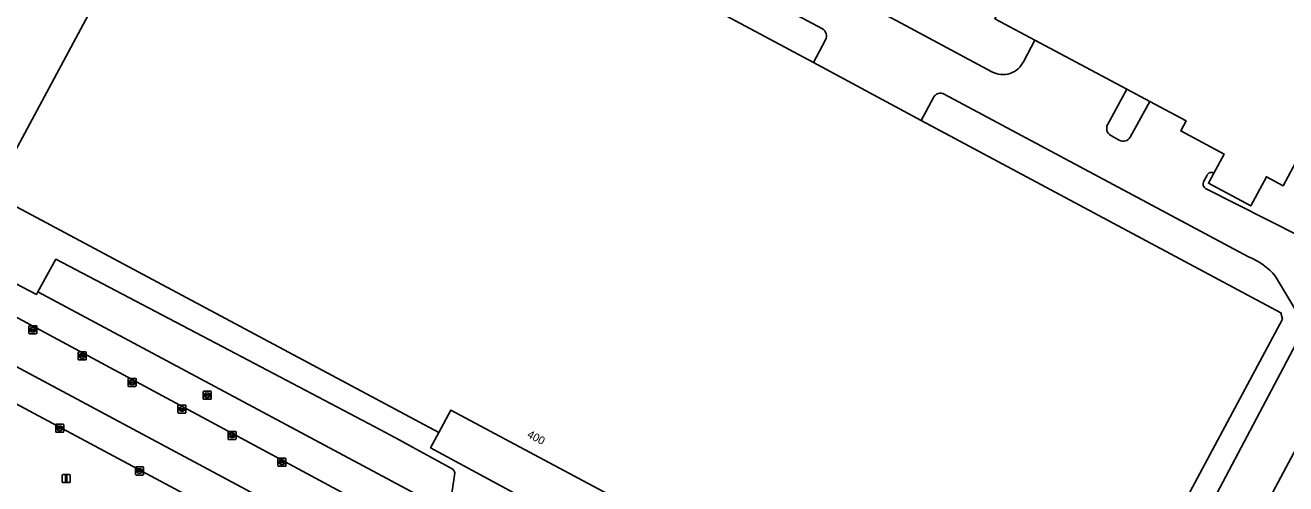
# Model space of a CAD drawing. Extents: x 159489 to 160304, y 383825 to 384531.
# Drawn here: x 159992.1 to 160149.6, y 383929.6 to 383987 of the extents above; entities that cross this region are included whole.
import ezdxf

# ---------------------------------------------------------------- set-up
doc = ezdxf.new("R2010")
doc.units = 0
for name, color, linetype in [('IMGEO_Brandkraan', 7, 'Continuous'), ('IMGEO_Kolk', 7, 'Continuous'), ('IMGEO_Lichtmast', 7, 'Continuous'), ('IMGEO_Pand', 7, 'Continuous'), ('IMGEO_Pand_nummerreeks', 7, 'Continuous'), ('IMGEO_Pand_overbouw', 7, 'Continuous'), ('IMGEO_Parkeervlak_open', 7, 'Continuous'), ('IMGEO_Rijbaan_lokaal_open', 7, 'Continuous'), ('IMGEO_Verkeerseiland_open', 7, 'Continuous'), ('IMGEO_Voetpad_open', 7, 'Continuous')]:
    doc.layers.add(name, color=color, linetype=linetype)

msp = doc.modelspace()

# ---------------------------------------------------------------- linework, layer by layer
at = {"layer": 'IMGEO_Brandkraan'}
for p, q in [((160014.34, 383940.27), (160014.34, 383941.12)), ((160014.42, 383941.2), (160015.27, 383941.2)), ((160014.6, 383940.69), (160014.6, 383940.7)), ((160014.64, 383940.74), (160015.04, 383940.74)), ((160015.04, 383940.65), (160014.64, 383940.65)), ((160014.83, 383940.98), (160014.85, 383940.98)), ((160014.85, 383940.42), (160014.83, 383940.42)), ((160015.08, 383940.7), (160015.08, 383940.69)), ((160015.34, 383941.12), (160015.34, 383940.27)), ((160015.27, 383940.2), (160014.42, 383940.2))]:
    msp.add_line(p, q, dxfattribs=at)
for points in [[(160014.34, 383940.27), (160014.34, 383941.12)], [(160014.42, 383941.2), (160015.27, 383941.2)], [(160015.34, 383941.12), (160015.34, 383940.27)], [(160015.27, 383940.2), (160014.42, 383940.2)]]:
    msp.add_lwpolyline(points, dxfattribs=at)
for centre, radius, start, end in [((160014.42, 383941.12), 0.0765, 91.552, 178.448), ((160014.42, 383941.12), 0.0765, 91.552, 178.448), ((160014.42, 383940.27), 0.0765, 181.552, 268.448), ((160014.42, 383940.27), 0.0765, 181.552, 268.448), ((160014.64, 383940.7), 0.0403, 85.8775, 175.7526), ((160014.64, 383940.69), 0.0366, 178.938, 274.7102), ((160015.05, 383940.7), 0.0386, 1.7309, 96.639), ((160015.04, 383940.7), 0.043, 264.8664, 352.4533), ((160015.27, 383941.12), 0.0765, 1.552, 88.448), ((160015.27, 383941.12), 0.0765, 1.552, 88.448), ((160015.27, 383940.27), 0.0765, 271.552, 358.448), ((160015.27, 383940.27), 0.0765, 271.552, 358.448)]:
    msp.add_arc(centre, radius, start, end, dxfattribs=at)
for centre, major_axis, ratio, start_param, end_param in [((160014.83, 383940.7), (-0.387, 0.002), 0.722429, 4.712389, 7.853982), ((160014.85, 383940.7), (-0.39, 0.002), 0.717154, 1.570796, 4.712389)]:
    msp.add_ellipse(centre, major_axis=major_axis, ratio=ratio, start_param=start_param, end_param=end_param, dxfattribs=at)
at = {"layer": 'IMGEO_Kolk'}
for p, q in [((159992.57, 383948.46), (159992.57, 383949.31)), ((159992.64, 383949.39), (159993.49, 383949.39)), ((159993.49, 383948.38), (159992.64, 383948.38)), ((159992.82, 383948.88), (159992.82, 383948.89)), ((159993.26, 383948.84), (159992.86, 383948.84)), ((159992.87, 383948.93), (159993.27, 383948.93)), ((159993.05, 383949.16), (159993.08, 383949.16)), ((159993.08, 383948.61), (159993.05, 383948.61)), ((159993.31, 383948.89), (159993.31, 383948.88)), ((159993.57, 383949.31), (159993.57, 383948.46)), ((159998.72, 383945.18), (159998.72, 383946.03)), ((159998.8, 383946.11), (159999.65, 383946.11)), ((159999.65, 383945.11), (159998.8, 383945.11)), ((159998.98, 383945.6), (159998.98, 383945.61)), ((159999.02, 383945.65), (159999.42, 383945.65)), ((159999.42, 383945.56), (159999.02, 383945.56)), ((159999.21, 383945.89), (159999.23, 383945.89)), ((159999.23, 383945.33), (159999.21, 383945.33)), ((159999.46, 383945.61), (159999.46, 383945.6)), ((159999.72, 383946.03), (159999.72, 383945.18)), ((160004.97, 383941.87), (160004.97, 383942.72)), ((160005.04, 383942.8), (160005.89, 383942.8)), ((160005.22, 383942.29), (160005.22, 383942.3)), ((160005.66, 383942.25), (160005.26, 383942.25)), ((160005.27, 383942.34), (160005.66, 383942.34)), ((160005.45, 383942.57), (160005.48, 383942.57)), ((160005.48, 383942.02), (160005.45, 383942.02)), ((160005.71, 383942.3), (160005.71, 383942.29)), ((160005.97, 383942.72), (160005.97, 383941.87)), ((160005.89, 383941.79), (160005.04, 383941.79)), ((160011.19, 383938.54), (160011.19, 383939.4)), ((160011.26, 383939.47), (160012.12, 383939.47)), ((160011.45, 383938.96), (160011.45, 383938.98)), ((160011.49, 383939.01), (160011.89, 383939.01)), ((160011.89, 383938.93), (160011.49, 383938.93)), ((160011.7, 383938.69), (160011.67, 383938.69)), ((160011.68, 383939.25), (160011.7, 383939.25)), ((160011.93, 383938.98), (160011.93, 383938.96)), ((160012.19, 383939.4), (160012.19, 383938.54)), ((160012.12, 383938.47), (160011.26, 383938.47)), ((159995.93, 383936.14), (159995.93, 383936.99)), ((159996, 383937.07), (159996.85, 383937.07)), ((159996.85, 383936.06), (159996, 383936.06)), ((159996.19, 383936.56), (159996.19, 383936.57)), ((159996.23, 383936.61), (159996.63, 383936.61)), ((159996.62, 383936.52), (159996.23, 383936.52)), ((159996.44, 383936.29), (159996.41, 383936.29)), ((159996.42, 383936.84), (159996.44, 383936.84)), ((159996.67, 383936.57), (159996.67, 383936.56)), ((159996.93, 383936.99), (159996.93, 383936.14)), ((160017.46, 383935.25), (160017.46, 383936.1)), ((160017.53, 383936.18), (160018.38, 383936.18)), ((160017.72, 383935.67), (160017.72, 383935.68)), ((160017.76, 383935.72), (160018.16, 383935.72)), ((160018.15, 383935.63), (160017.76, 383935.63)), ((160017.95, 383935.96), (160017.97, 383935.96)), ((160018.2, 383935.68), (160018.2, 383935.67)), ((160018.46, 383936.1), (160018.46, 383935.25)), ((160018.38, 383935.18), (160017.53, 383935.18)), ((160017.97, 383935.4), (160017.94, 383935.4)), ((160023.69, 383931.89), (160023.69, 383932.74)), ((160023.76, 383932.82), (160024.62, 383932.82)), ((160023.99, 383932.36), (160024.39, 383932.36)), ((160024.18, 383932.6), (160024.2, 383932.6)), ((160024.69, 383932.74), (160024.69, 383931.89)), ((160005.88, 383930.8), (160005.88, 383931.65)), ((160005.96, 383931.73), (160006.81, 383931.73)), ((160006.14, 383931.22), (160006.14, 383931.23)), ((160006.58, 383931.18), (160006.18, 383931.18)), ((160006.19, 383931.27), (160006.58, 383931.27)), ((160006.37, 383931.5), (160006.4, 383931.5)), ((160006.39, 383930.95), (160006.37, 383930.95)), ((160006.63, 383931.23), (160006.63, 383931.22)), ((160006.88, 383931.65), (160006.88, 383930.8)), ((160024.62, 383931.82), (160023.76, 383931.82)), ((160023.95, 383932.31), (160023.95, 383932.32)), ((160024.38, 383932.27), (160023.99, 383932.27)), ((160024.2, 383932.04), (160024.17, 383932.04)), ((160024.43, 383932.32), (160024.43, 383932.31)), ((160006.81, 383930.72), (160005.96, 383930.72))]:
    msp.add_line(p, q, dxfattribs=at)
for points in [[(159992.57, 383948.46), (159992.57, 383949.31)], [(159992.64, 383949.39), (159993.49, 383949.39)], [(159993.49, 383948.38), (159992.64, 383948.38)], [(159993.57, 383949.31), (159993.57, 383948.46)], [(159998.72, 383945.18), (159998.72, 383946.03)], [(159998.8, 383946.11), (159999.65, 383946.11)], [(159999.65, 383945.11), (159998.8, 383945.11)], [(159999.72, 383946.03), (159999.72, 383945.18)], [(160004.97, 383941.87), (160004.97, 383942.72)], [(160005.04, 383942.8), (160005.89, 383942.8)], [(160005.97, 383942.72), (160005.97, 383941.87)], [(160005.89, 383941.79), (160005.04, 383941.79)], [(160011.19, 383938.54), (160011.19, 383939.4)], [(160011.26, 383939.47), (160012.12, 383939.47)], [(160012.19, 383939.4), (160012.19, 383938.54)], [(160012.12, 383938.47), (160011.26, 383938.47)], [(159995.93, 383936.14), (159995.93, 383936.99)], [(159996, 383937.07), (159996.85, 383937.07)], [(159996.85, 383936.06), (159996, 383936.06)], [(159996.93, 383936.99), (159996.93, 383936.14)], [(160017.46, 383935.25), (160017.46, 383936.1)], [(160017.53, 383936.18), (160018.38, 383936.18)], [(160018.46, 383936.1), (160018.46, 383935.25)], [(160018.38, 383935.18), (160017.53, 383935.18)], [(160023.69, 383931.89), (160023.69, 383932.74)], [(160023.76, 383932.82), (160024.62, 383932.82)], [(160024.69, 383932.74), (160024.69, 383931.89)], [(160005.88, 383930.8), (160005.88, 383931.65)], [(160005.96, 383931.73), (160006.81, 383931.73)], [(160006.88, 383931.65), (160006.88, 383930.8)], [(160024.62, 383931.82), (160023.76, 383931.82)], [(160006.81, 383930.72), (160005.96, 383930.72)]]:
    msp.add_lwpolyline(points, dxfattribs=at)
for centre, radius, start, end in [((159992.64, 383949.31), 0.0765, 91.552, 178.448), ((159992.64, 383949.31), 0.0765, 91.552, 178.448), ((159992.64, 383948.46), 0.0765, 181.552, 268.448), ((159992.64, 383948.46), 0.0765, 181.552, 268.448), ((159992.87, 383948.89), 0.0403, 85.8775, 175.7526), ((159992.86, 383948.88), 0.0366, 178.938, 274.7102), ((159993.27, 383948.88), 0.043, 264.8664, 352.4533), ((159993.27, 383948.89), 0.0386, 1.7309, 96.639), ((159993.49, 383949.31), 0.0765, 1.552, 88.448), ((159993.49, 383949.31), 0.0765, 1.552, 88.448), ((159993.49, 383948.46), 0.0765, 271.552, 358.448), ((159993.49, 383948.46), 0.0765, 271.552, 358.448), ((159998.8, 383946.03), 0.0765, 91.552, 178.448), ((159998.8, 383946.03), 0.0765, 91.552, 178.448), ((159998.8, 383945.18), 0.0765, 181.552, 268.448), ((159998.8, 383945.18), 0.0765, 181.552, 268.448), ((159999.02, 383945.61), 0.0403, 85.8775, 175.7526), ((159999.02, 383945.6), 0.0366, 178.938, 274.7102), ((159999.43, 383945.61), 0.0386, 1.7309, 96.639), ((159999.42, 383945.61), 0.043, 264.8664, 352.4533), ((159999.65, 383946.03), 0.0765, 1.552, 88.448), ((159999.65, 383946.03), 0.0765, 1.552, 88.448), ((159999.65, 383945.18), 0.0765, 271.552, 358.448), ((159999.65, 383945.18), 0.0765, 271.552, 358.448), ((160005.04, 383942.72), 0.0765, 91.552, 178.448), ((160005.04, 383942.72), 0.0765, 91.552, 178.448), ((160005.04, 383941.87), 0.0765, 181.552, 268.448), ((160005.04, 383941.87), 0.0765, 181.552, 268.448), ((160005.26, 383942.3), 0.0403, 85.8775, 175.7526), ((160005.26, 383942.29), 0.0366, 178.938, 274.7102), ((160005.67, 383942.3), 0.0386, 1.7309, 96.639), ((160005.67, 383942.29), 0.043, 264.8664, 352.4533), ((160005.89, 383942.72), 0.0765, 1.552, 88.448), ((160005.89, 383942.72), 0.0765, 1.552, 88.448), ((160005.89, 383941.87), 0.0765, 271.552, 358.448), ((160005.89, 383941.87), 0.0765, 271.552, 358.448), ((160011.27, 383939.39), 0.0765, 91.552, 178.448), ((160011.27, 383939.39), 0.0765, 91.552, 178.448), ((160011.49, 383938.97), 0.0403, 85.8775, 175.7526), ((160011.48, 383938.96), 0.0366, 178.938, 274.7102), ((160011.89, 383938.97), 0.0386, 1.7309, 96.639), ((160011.89, 383938.97), 0.043, 264.8664, 352.4533), ((160012.11, 383939.39), 0.0765, 1.552, 88.448), ((160012.11, 383939.39), 0.0765, 1.552, 88.448), ((160011.27, 383938.54), 0.0765, 181.552, 268.448), ((160011.27, 383938.54), 0.0765, 181.552, 268.448), ((160012.11, 383938.54), 0.0765, 271.552, 358.448), ((160012.11, 383938.54), 0.0765, 271.552, 358.448), ((159996, 383936.99), 0.0765, 91.552, 178.448), ((159996, 383936.99), 0.0765, 91.552, 178.448), ((159996, 383936.14), 0.0765, 181.552, 268.448), ((159996, 383936.14), 0.0765, 181.552, 268.448), ((159996.23, 383936.57), 0.0403, 85.8775, 175.7526), ((159996.22, 383936.56), 0.0366, 178.938, 274.7102), ((159996.63, 383936.56), 0.043, 264.8664, 352.4533), ((159996.63, 383936.57), 0.0386, 1.7309, 96.639), ((159996.85, 383936.99), 0.0765, 1.552, 88.448), ((159996.85, 383936.99), 0.0765, 1.552, 88.448), ((159996.85, 383936.14), 0.0765, 271.552, 358.448), ((159996.85, 383936.14), 0.0765, 271.552, 358.448), ((160017.53, 383936.1), 0.0765, 91.552, 178.448), ((160017.53, 383936.1), 0.0765, 91.552, 178.448), ((160017.76, 383935.68), 0.0403, 85.8775, 175.7526), ((160017.75, 383935.67), 0.0366, 178.938, 274.7102), ((160018.16, 383935.68), 0.043, 264.8664, 352.4533), ((160018.16, 383935.68), 0.0386, 1.7309, 96.639), ((160018.38, 383936.1), 0.0765, 1.552, 88.448), ((160018.38, 383936.1), 0.0765, 1.552, 88.448), ((160017.53, 383935.25), 0.0765, 181.552, 268.448), ((160017.53, 383935.25), 0.0765, 181.552, 268.448), ((160018.38, 383935.25), 0.0765, 271.552, 358.448), ((160018.38, 383935.25), 0.0765, 271.552, 358.448), ((160023.76, 383932.74), 0.0765, 91.552, 178.448), ((160023.76, 383932.74), 0.0765, 91.552, 178.448), ((160023.99, 383932.32), 0.0403, 85.8775, 175.7526), ((160024.39, 383932.32), 0.0386, 1.7309, 96.639), ((160024.61, 383932.74), 0.0765, 1.552, 88.448), ((160024.61, 383932.74), 0.0765, 1.552, 88.448), ((160005.96, 383931.65), 0.0765, 91.552, 178.448), ((160005.96, 383931.65), 0.0765, 91.552, 178.448), ((160005.96, 383930.8), 0.0765, 181.552, 268.448), ((160005.96, 383930.8), 0.0765, 181.552, 268.448), ((160006.18, 383931.23), 0.0403, 85.8775, 175.7526), ((160006.18, 383931.22), 0.0366, 178.938, 274.7102), ((160006.59, 383931.23), 0.0386, 1.7309, 96.639), ((160006.58, 383931.22), 0.043, 264.8664, 352.4533), ((160006.81, 383931.65), 0.0765, 1.552, 88.448), ((160006.81, 383931.65), 0.0765, 1.552, 88.448), ((160006.81, 383930.8), 0.0765, 271.552, 358.448), ((160006.81, 383930.8), 0.0765, 271.552, 358.448), ((160023.76, 383931.89), 0.0765, 181.552, 268.448), ((160023.76, 383931.89), 0.0765, 181.552, 268.448), ((160023.98, 383932.31), 0.0366, 178.938, 274.7102), ((160024.39, 383932.32), 0.043, 264.8664, 352.4533), ((160024.61, 383931.89), 0.0765, 271.552, 358.448), ((160024.61, 383931.89), 0.0765, 271.552, 358.448)]:
    msp.add_arc(centre, radius, start, end, dxfattribs=at)
for centre, major_axis, ratio, start_param, end_param in [((159993.05, 383948.88), (-0.387, 0.002), 0.722429, 4.712389, 7.853982), ((159993.08, 383948.88), (-0.39, 0.002), 0.717154, 1.570796, 4.712389), ((159999.21, 383945.61), (-0.387, 0.002), 0.722429, 4.712389, 7.853982), ((159999.23, 383945.61), (-0.39, 0.002), 0.717154, 1.570796, 4.712389), ((160005.45, 383942.29), (-0.387, 0.002), 0.722429, 4.712389, 7.853982), ((160005.48, 383942.29), (-0.39, 0.002), 0.717154, 1.570796, 4.712389), ((160011.68, 383938.97), (-0.387, 0.002), 0.722429, 4.712389, 7.853982), ((160011.7, 383938.97), (-0.39, 0.002), 0.717154, 1.570796, 4.712389), ((159996.41, 383936.56), (-0.387, 0.002), 0.722429, 4.712389, 7.853982), ((159996.44, 383936.56), (-0.39, 0.002), 0.717154, 1.570796, 4.712389), ((160017.94, 383935.68), (-0.387, 0.002), 0.722429, 4.712389, 7.853982), ((160017.97, 383935.68), (-0.39, 0.002), 0.717154, 1.570796, 4.712389), ((160024.18, 383932.32), (-0.387, 0.002), 0.722429, 4.712389, 7.853982), ((160024.2, 383932.32), (-0.39, 0.002), 0.717154, 1.570796, 4.712389), ((160006.37, 383931.22), (-0.387, 0.002), 0.722429, 4.712389, 7.853982), ((160006.39, 383931.22), (-0.39, 0.002), 0.717154, 1.570796, 4.712389)]:
    msp.add_ellipse(centre, major_axis=major_axis, ratio=ratio, start_param=start_param, end_param=end_param, dxfattribs=at)
at = {"layer": 'IMGEO_Lichtmast'}
for p, q in [((159996.82, 383930.77), (159997.61, 383930.77)), ((159997.61, 383930.77), (159996.82, 383930.77)), ((159996.72, 383929.87), (159996.72, 383930.67)), ((159996.72, 383930.67), (159996.72, 383929.87)), ((159997.61, 383929.77), (159996.82, 383929.77)), ((159996.82, 383929.77), (159997.61, 383929.77)), ((159997.71, 383930.67), (159997.71, 383929.87)), ((159997.71, 383929.87), (159997.71, 383930.67))]:
    msp.add_line(p, q, dxfattribs=at)
msp.add_lwpolyline([(159997.14, 383930.65), (159997.29, 383930.65), (159997.29, 383929.9), (159997.14, 383929.9), (159997.14, 383930.65)], dxfattribs=at)
for centre, start, end in [((159996.82, 383930.67), 90, 180), ((159996.82, 383930.67), 90, 180), ((159997.61, 383930.67), 0, 90), ((159997.61, 383930.67), 360, 90), ((159996.82, 383929.87), 180, 270), ((159996.82, 383929.87), 180, 270), ((159997.61, 383929.87), 270, 0), ((159997.61, 383929.87), 270, 0)]:
    msp.add_arc(centre, 0.1, start, end, dxfattribs=at)
at = {"layer": 'IMGEO_Pand'}
msp.add_lwpolyline([(160129.76, 383978.95), (160132.63, 383977.41), (160137.17, 383974.99), (160136.51, 383973.74), (160141.91, 383970.85), (160140.64, 383968.48), (160139.96, 383967.19), (160145.25, 383964.37), (160147.2, 383968.02), (160149.32, 383966.89), (160167.11, 384000.17), (160166.14, 384000.69), (160167.74, 384003.68), (160168.71, 384003.16), (160170.75, 384006.97), (160158.03, 384013.79), (160157.89, 384013.52), (160133.95, 384026.36), (160113.25, 383987.77), (160118.27, 383985.09)], close=True, dxfattribs=at)
for points in [[(159988.49, 383965.57), (159995.29, 383961.94), (160043.8, 383936.05), (160045.31, 383938.84), (160065.57, 383928.01), (160064.04, 383925.22), (160112.85, 383899.1), (160119.34, 383895.63), (160120.16, 383895.88), (160149.23, 383950.19), (160149, 383951.01), (160104.06, 383975.06), (160090.59, 383982.28), (160018.18, 384021.04)], [(160002.95, 383993.83), (159989.33, 383968.4)]]:
    msp.add_lwpolyline(points, dxfattribs=at)
at = {"layer": 'IMGEO_Pand_overbouw'}
msp.add_lwpolyline([(160045.31, 383938.84), (160043.8, 383936.05), (160042.76, 383934.13), (160062.95, 383923.21), (160064.04, 383925.22), (160065.57, 383928.01)], close=True, dxfattribs=at)
at = {"layer": 'IMGEO_Parkeervlak_open'}
for points in [[(160017.6, 383946.32), (159995.94, 383957.7), (159993.67, 383953.62), (160045.07, 383926.11), (160045.78, 383930.98)], [(160037.66, 383925.31), (159978.66, 383957.07)], [(159974.43, 383953.14), (160033.77, 383921.35)], [(160029.55, 383918.93), (159972.63, 383949.42)], [(160045.53, 383931.43), (160040.49, 383934.22), (160038.9, 383935.08), (160035.8, 383936.73), (160017.6, 383946.32)]]:
    msp.add_lwpolyline(points, dxfattribs=at)
msp.add_arc((160045.21, 383930.96), 0.574, 1.8948, 55.6785, dxfattribs=at)
at = {"layer": 'IMGEO_Rijbaan_lokaal_open'}
for points in [[(160112.89, 383981.13), (160102.73, 383986.6), (160101.57, 383987.22), (160080.06, 383998.71), (160080.04, 383998.72), (160063.16, 384007.77), (160060.19, 384009.34), (160049.33, 384015.21), (160034.85, 384022.89), (160024.96, 384028.21), (160022.6, 384029.44), (160021.95, 384029.79), (160020.34, 384030.65), (160018.33, 384031.73), (160014.38, 384030.54), (160008.13, 384028.67), (160007.67, 384028.53), (160006.58, 384028.19), (160003.8, 384027.33), (160002.83, 384027.04)], [(159989.33, 383968.4), (160002.95, 383993.83), (160003.94, 383993.3), (160011.18, 384006.86), (160010.58, 384007.18), (160010.48, 384006.98), (160010.09, 384007.19), (160010.19, 384007.39), (160009.52, 384007.74), (160009.18, 384007.11), (160005.05, 384009.43), (160005.52, 384010.27), (160005.79, 384010.49), (160006.12, 384010.47), (160008.09, 384009.41), (160011.4, 384015.58), (160013.87, 384014.26), (160016.31, 384018.83), (160013.85, 384020.15), (160015.81, 384023.64)], [(160051.05, 384008.29), (160054.05, 384006.68), (160056.2, 384002.21), (160060.32, 384000), (160066.87, 383996.49), (160071, 383997.6), (160091.72, 383986.49)], [(160092.13, 383985.14), (160090.59, 383982.28), (160104.06, 383975.06), (160105.59, 383977.92)], [(160127.36, 383974.52), (160129.76, 383978.95), (160118.27, 383985.09), (160116.88, 383982.46)], [(160106.95, 383978.33), (160144.98, 383957.98)], [(160140.64, 383968.48), (160141.91, 383970.85), (160136.51, 383973.74), (160137.17, 383974.99), (160132.63, 383977.41), (160130.19, 383972.97)], [(160128.82, 383972.58), (160127.75, 383973.17)], [(160045.07, 383926.11), (159993.67, 383953.62), (159993.5, 383953.31), (159981.38, 383959.62), (159983.84, 383964.06), (159985.87, 383967.7), (159979.72, 383970.99), (159977.69, 383967.23), (159976.47, 383964.96), (159973.79, 383959.68)], [(160139.36, 383967.36), (160139.81, 383968.23)], [(160194.88, 383931.74), (160195.65, 383933.58), (160196.71, 383936.36), (160196.51, 383936.47), (160178.83, 383945.95), (160161.11, 383955.42), (160157.94, 383957.17), (160151.4, 383960.58), (160139.61, 383966.55)], [(159978.66, 383957.07), (160037.66, 383925.31), (160037.76, 383925.26), (160037.97, 383925.12), (160041.55, 383923.21)], [(160148.35, 383955.56), (160151.23, 383950.76), (160151.52, 383950.04), (160151.63, 383949.27), (160151.55, 383948.5), (160151.28, 383947.77), (160136.85, 383920.54), (160142.15, 383917.59), (160153.27, 383938.4), (160158.15, 383947.47), (160189.76, 383930.48), (160189.33, 383929.35), (160183.8, 383919.1)], [(160035.64, 383920.37), (160033.77, 383921.35), (159974.43, 383953.14)], [(159972.21, 383949.67), (159972.47, 383949.51), (159972.63, 383949.42), (160029.55, 383918.93)]]:
    msp.add_lwpolyline(points, dxfattribs=at)
for centre, radius, start, end in [((160091.24, 383985.61), 1, 331.942, 61.6196), ((160114.27, 383983.66), 2.87, 241.5088, 335.318), ((160106.47, 383977.45), 0.999, 61.8678, 151.8725), ((160128.24, 383974.05), 0.998, 151.3891, 241.0498), ((160129.31, 383973.45), 1, 240.8038, 331.2645), ((160139.89, 383967.08), 0.599, 152.4915, 241.9735), ((160140.34, 383967.96), 0.601, 59.928, 152.4341), ((160141.95, 383950.2), 8.35, 39.9323, 68.7229)]:
    msp.add_arc(centre, radius, start, end, dxfattribs=at)
at = {"layer": 'IMGEO_Verkeerseiland_open'}
for points in [[(160130.19, 383972.97), (160132.63, 383977.41), (160129.76, 383978.95), (160127.36, 383974.52)], [(160127.75, 383973.17), (160128.82, 383972.58)]]:
    msp.add_lwpolyline(points, dxfattribs=at)
for centre, radius, start, end in [((160128.24, 383974.05), 0.998, 151.3891, 241.0498), ((160129.31, 383973.45), 1, 240.8038, 331.2645)]:
    msp.add_arc(centre, radius, start, end, dxfattribs=at)
at = {"layer": 'IMGEO_Voetpad_open'}
for points in [[(160015.81, 384023.64), (160013.85, 384020.15), (160016.31, 384018.83), (160017.35, 384020.78), (160018.18, 384021.04), (160090.59, 383982.28), (160092.13, 383985.14)], [(160091.72, 383986.49), (160071, 383997.6), (160066.87, 383996.49), (160060.32, 384000), (160056.2, 384002.21), (160054.05, 384006.68), (160051.05, 384008.29)], [(160184.53, 383995.55), (160185.31, 383995.13), (160187, 383998.31), (160170.75, 384006.97), (160168.71, 384003.16), (160167.74, 384003.68), (160166.14, 384000.69), (160167.11, 384000.17), (160149.32, 383966.89), (160147.2, 383968.02), (160145.25, 383964.37), (160139.96, 383967.19), (160140.64, 383968.48)], [(160080.04, 383998.72), (160080.06, 383998.71), (160101.57, 383987.22), (160102.73, 383986.6), (160112.89, 383981.13)], [(160116.88, 383982.46), (160118.27, 383985.09), (160113.25, 383987.77)], [(160144.98, 383957.98), (160106.95, 383978.33)], [(160105.59, 383977.92), (160104.06, 383975.06), (160149, 383951.01), (160149.23, 383950.19), (160120.16, 383895.88), (160119.34, 383895.63), (160112.85, 383899.1), (160064.04, 383925.22), (160065.57, 383928.01), (160045.31, 383938.84)], [(160045.31, 383938.84), (160043.8, 383936.05), (159995.29, 383961.94), (159988.49, 383965.57), (159988.3, 383966.46), (159989.33, 383968.4), (159986.97, 383969.68), (159985.87, 383967.7), (159983.84, 383964.06), (159981.38, 383959.62), (159993.5, 383953.31), (159993.67, 383953.62), (159995.94, 383957.7), (160017.6, 383946.32), (160035.8, 383936.73), (160038.9, 383935.08), (160040.49, 383934.22), (160045.53, 383931.43)], [(160139.81, 383968.23), (160139.36, 383967.36)], [(160139.61, 383966.55), (160151.4, 383960.58)], [(160122, 383892.77), (160126.18, 383900.69), (160135.17, 383917.45), (160136.85, 383920.54), (160151.28, 383947.77), (160151.55, 383948.5), (160151.63, 383949.27), (160151.52, 383950.04), (160151.23, 383950.76), (160148.35, 383955.56)], [(160183.8, 383919.1), (160189.33, 383929.35), (160189.76, 383930.48), (160158.15, 383947.47), (160153.27, 383938.4), (160142.15, 383917.59), (160140.53, 383914.58), (160127.74, 383890.68)], [(160045.78, 383930.98), (160045.07, 383926.11)]]:
    msp.add_lwpolyline(points, dxfattribs=at)
for centre, radius, start, end in [((160091.24, 383985.61), 1, 331.942, 61.6196), ((160114.27, 383983.66), 2.87, 241.5088, 335.318), ((160106.47, 383977.45), 0.999, 61.8678, 151.8725), ((160139.89, 383967.08), 0.599, 152.4915, 241.9735), ((160140.34, 383967.96), 0.601, 59.928, 152.4341), ((160141.95, 383950.2), 8.35, 39.9323, 68.7229), ((160045.21, 383930.96), 0.574, 1.8948, 55.6785)]:
    msp.add_arc(centre, radius, start, end, dxfattribs=at)

# ---------------------------------------------------------------- texts
at = {"layer": 'IMGEO_Pand_nummerreeks'}
msp.add_text('400', height=1, rotation=331.8735, dxfattribs=at).set_placement((160054.74, 383935.5))

doc.saveas('drawing.dxf')
